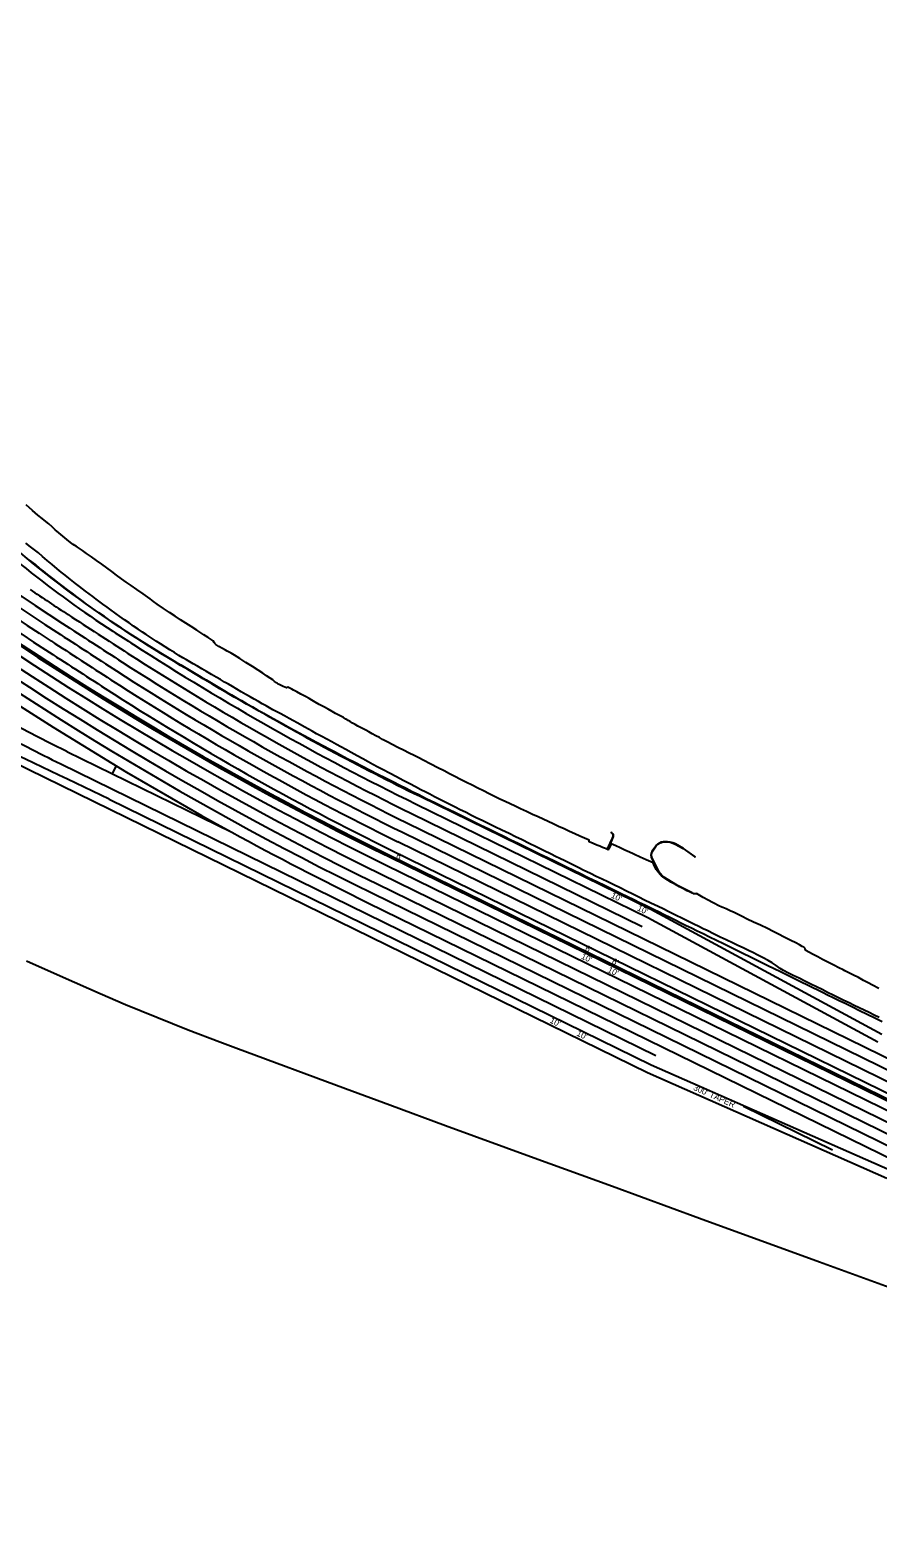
# Model space of a CAD drawing. Extents: x -5665 to 1997148, y 4 to 812485.
# Drawn here: x 1972202 to 1973176, y 793991 to 795722 of the extents above; entities that cross this region are included whole.
import ezdxf

# ---------------------------------------------------------------- set-up
doc = ezdxf.new("R2010")
doc.units = 0
for name, color, linetype in [('RD_EX_Conc', 7, 'Continuous'), ('RD_EX_RailRoad', 7, 'Continuous'), ('RD_EX_Road', 7, 'Continuous'), ('RD_PD_ALT1_TrvlWay', 7, 'Continuous'), ('RD_PD_Final_LnLine', 7, 'Continuous'), ('RD_PD_MedBWall', 7, 'Continuous'), ('RD_PD_PaveShd', 7, 'Continuous'), ('RD_SHT_TX', 7, 'Continuous')]:
    doc.layers.add(name, color=color, linetype=linetype)

msp = doc.modelspace()

# ---------------------------------------------------------------- linework, layer by layer
at = {"layer": 'RD_EX_Conc'}
for points in [[(1972864.5, 794783.6), (1972865.7, 794783.1), (1972867, 794785.4), (1972870, 794792.2), (1972870.2, 794792.5), (1972871.8, 794796.2), (1972871.9, 794797.2), (1972871.8, 794798.4), (1972871.3, 794799.5), (1972870.4, 794800.4), (1972869.4, 794801), (1972870.4, 794800.4), (1972871.3, 794799.5), (1972871.8, 794798.4), (1972872, 794797.2), (1972871.9, 794796.2), (1972870.3, 794792.5), (1972867.1, 794785.4), (1972865.8, 794783), (1972864.5, 794783.5)], [(1972965.3, 794773.6), (1972966, 794773.2), (1972952.5, 794782.7), (1972943.3, 794787.8), (1972940.4, 794789), (1972937.3, 794789.8), (1972934.2, 794790.3), (1972931.7, 794790.3), (1972929.4, 794790.2), (1972927.1, 794789.7), (1972927.1, 794789.7), (1972925, 794788.8), (1972923, 794787.5), (1972921.3, 794786), (1972921.1, 794785.8), (1972916.4, 794779), (1972915.8, 794777.1), (1972915.5, 794775.1), (1972915.7, 794773.1), (1972915.9, 794772.1), (1972924.1, 794756), (1972925.9, 794753.5), (1972928.1, 794751.2), (1972930.5, 794749.3), (1972930.6, 794749.2), (1972945.7, 794740.2), (1972962.5, 794731.9), (1972962.5, 794731.9), (1972945.8, 794740.3), (1972930.7, 794749.3), (1972930.5, 794749.4), (1972928.1, 794751.3), (1972926, 794753.5), (1972924.2, 794756), (1972916, 794772.2), (1972915.8, 794773.1), (1972915.6, 794775.1), (1972915.9, 794777.1), (1972916.5, 794778.9), (1972921.2, 794785.8), (1972921.4, 794785.9), (1972923.1, 794787.5), (1972925, 794788.7), (1972927.1, 794789.6), (1972927.2, 794789.6), (1972929.4, 794790.1), (1972931.7, 794790.2), (1972934.2, 794790.2), (1972937.3, 794789.7), (1972940.3, 794788.9), (1972943.2, 794787.7), (1972952.4, 794782.6), (1972965.3, 794773.6)]]:
    msp.add_lwpolyline(points, dxfattribs=at)
at = {"layer": 'RD_EX_RailRoad'}
msp.add_lwpolyline([(1972198.4, 794653.7), (1972240.5, 794634.8), (1972282.8, 794616.2), (1972311.9, 794603.6), (1972347.9, 794589), (1972384, 794574.6), (1972420.3, 794560.7), (1972438.6, 794553.8), (1972564.6, 794507.3), (1972615.3, 794488.4), (1972679.2, 794464.8), (1972781.1, 794427.7), (1972871, 794395), (1972971, 794358.5), (1973108.6, 794308.1), (1973213.8, 794269.9)], dxfattribs=at)
at = {"layer": 'RD_EX_Road'}
for points in [[(1973176.9, 794622), (1973169.6, 794625.7), (1973164.6, 794628.3), (1973159.1, 794631.3), (1973153.4, 794634.4), (1973147.8, 794637.3), (1973142.5, 794640), (1973138, 794642.3), (1973135.8, 794643.4), (1973130.9, 794645.8), (1973125.3, 794648.6), (1973119.2, 794651.7), (1973112.1, 794655.4), (1973107, 794658.1), (1973100.6, 794661.5), (1973093.1, 794665.6), (1973092.4, 794667.4), (1973092.1, 794667.9), (1973091.9, 794668.2), (1973091.6, 794668.6), (1973091.2, 794669), (1973090.8, 794669.3), (1973088.9, 794670.3), (1973085.8, 794672), (1973081.4, 794674.2), (1973075.8, 794677), (1973068.8, 794680.6), (1973060.8, 794684.8), (1973055.5, 794687.5), (1973048.9, 794690.8), (1973041.1, 794694.5), (1973033.1, 794698.2), (1973025.8, 794701.6), (1973020.1, 794704.4), (1973015.3, 794706.8), (1973010.8, 794709), (1973006.3, 794711.1), (1973001.6, 794713.2), (1972997.9, 794714.8), (1972996.5, 794715.4), (1972995.8, 794715.7), (1972994.1, 794716.5), (1972991.8, 794717.6), (1972989.1, 794719), (1972985.7, 794720.8), (1972981.1, 794723.2), (1972975.1, 794726.5), (1972967.4, 794730.8), (1972967, 794730.7), (1972966.6, 794730.6), (1972965.6, 794730.6), (1972965.1, 794730.6), (1972964.7, 794730.6), (1972964.2, 794730.7), (1972963.8, 794730.9), (1972962.5, 794731.4), (1972960.2, 794732.6), (1972956.9, 794734.2), (1972952.8, 794736.2), (1972948, 794738.7), (1972943.3, 794741.2), (1972938.2, 794744.1), (1972934.5, 794746.2), (1972931.6, 794748), (1972929.4, 794749.6), (1972927.5, 794751.2), (1972925.9, 794752.8), (1972924.4, 794754.6), (1972922.8, 794756.5), (1972921.4, 794758.6), (1972920.2, 794760.7), (1972919, 794763.1), (1972917.6, 794766.2), (1972909.9, 794769.5), (1972902.8, 794772.7), (1972896.4, 794775.6), (1972894.7, 794776.4), (1972890.7, 794778.3), (1972885.3, 794780.8), (1972880, 794783.3), (1972874.8, 794785.7), (1972869.7, 794788), (1972868.5, 794785.4), (1972866.8, 794782.5), (1972866, 794781.2), (1972865.2, 794781.6), (1972863.9, 794782.1), (1972862, 794782.9), (1972859.7, 794783.9), (1972856.7, 794785.1), (1972855.5, 794785.6), (1972853.2, 794786.5), (1972849, 794788.2), (1972844.2, 794790.2), (1972844.3, 794792), (1972839.1, 794794.4), (1972833.5, 794796.9), (1972827.7, 794799.6), (1972821.8, 794802.2), (1972815.7, 794805), (1972809.2, 794808), (1972802.9, 794810.9), (1972797.2, 794813.5), (1972791.6, 794816.1), (1972785.8, 794818.8), (1972779.4, 794821.7), (1972772.4, 794825), (1972765.3, 794828.3), (1972759.2, 794831.1), (1972753.5, 794833.8), (1972747.7, 794836.5), (1972741.7, 794839.4), (1972735.6, 794842.4), (1972729.4, 794845.5), (1972722.9, 794848.7), (1972716.4, 794852), (1972710, 794855.2), (1972703.4, 794858.5), (1972696.7, 794861.9), (1972690, 794865.2), (1972684, 794868.3), (1972677.7, 794871.6), (1972670.5, 794875.3), (1972662.4, 794879.5), (1972653.6, 794884), (1972648.8, 794886.5), (1972643.4, 794889.2), (1972637.6, 794892.2), (1972631.3, 794895.4), (1972625.4, 794898.3), (1972617.5, 794902.4), (1972614, 794904.2), (1972610.8, 794905.9), (1972607.2, 794907.8), (1972603.4, 794909.9), (1972599.2, 794912.1), (1972595.2, 794914.3), (1972591.3, 794916.5), (1972587.9, 794918.3), (1972584.9, 794919.8), (1972581.9, 794921.4), (1972578.8, 794923.1), (1972575.7, 794924.8), (1972572.7, 794926.6), (1972569.9, 794928.3), (1972567.7, 794929.6), (1972566.1, 794930.6), (1972565, 794931.2), (1972562.1, 794932.8), (1972557.6, 794935.3), (1972553.2, 794937.7), (1972549.1, 794940), (1972544.5, 794942.5), (1972539.5, 794945.2), (1972534.5, 794948), (1972529.8, 794950.6), (1972525.9, 794952.8), (1972522.7, 794954.6), (1972518.5, 794956.9), (1972513.2, 794959.8), (1972508.7, 794962.3), (1972504.9, 794964.4), (1972502.9, 794965.5), (1972498.4, 794967.9), (1972496.9, 794967.1), (1972494.9, 794967.9), (1972493.1, 794968.6), (1972491.4, 794969.4), (1972489.9, 794970.1), (1972488.5, 794970.8), (1972487.3, 794971.4), (1972486, 794972.2), (1972485.1, 794972.7), (1972484.2, 794973.4), (1972483.1, 794974.4), (1972481.3, 794976), (1972478, 794978.2), (1972474, 794980.9), (1972469.7, 794983.7), (1972464.4, 794987.1), (1972457.6, 794991.4), (1972450.1, 794996.1), (1972443.2, 795000.6), (1972437.3, 795004.4), (1972433.1, 795006.8), (1972430.4, 795008.3), (1972428.8, 795009.1), (1972426.9, 795010.1), (1972423.2, 795012.2), (1972419.3, 795014.4), (1972416.7, 795016.1), (1972415.7, 795016.9), (1972414.7, 795018), (1972413.8, 795019.2), (1972412.8, 795020.8), (1972406.9, 795024.6), (1972401.8, 795028), (1972393.7, 795033.2), (1972387.3, 795037.3), (1972381.2, 795041.2), (1972375.2, 795045.1), (1972369, 795049.3), (1972362.5, 795053.6), (1972355.7, 795058.2), (1972348.3, 795063.2), (1972344.3, 795066), (1972340.2, 795069), (1972332.1, 795074.8), (1972324.9, 795079.9), (1972318.6, 795084.3), (1972312.9, 795088.3), (1972307.5, 795092.2), (1972301.8, 795096.3), (1972296.1, 795100.5), (1972290.4, 795104.7), (1972284.7, 795108.8), (1972278.8, 795113), (1972273, 795117.2), (1972267.3, 795121.3), (1972262.5, 795124.8), (1972259, 795127.1), (1972256.7, 795128.5), (1972255.3, 795129.5), (1972253.9, 795130.3), (1972252, 795131.6), (1972249, 795133.8), (1972244.7, 795137.2), (1972239.9, 795141.2), (1972235.3, 795145), (1972231.2, 795148.5), (1972227.6, 795151.9), (1972224.1, 795155.1), (1972220.5, 795158.1), (1972216.3, 795161.3), (1972211.4, 795165.3), (1972205.3, 795170.4), (1972197.8, 795176.9)], [(1973177.4, 794588.5), (1973171.5, 794591.4), (1973165.6, 794594.2), (1973159.9, 794597), (1973154.2, 794599.8), (1973148.5, 794602.6), (1973142.7, 794605.4), (1973136.7, 794608.3), (1973130.7, 794611.3), (1973124.4, 794614.3), (1973118.1, 794617.4), (1973111.7, 794620.6), (1973105.2, 794623.8), (1973098.6, 794627), (1973091.9, 794630.3), (1973085.2, 794633.6), (1973078.5, 794636.9), (1973072.4, 794640), (1973067.4, 794642.6), (1973063.6, 794644.9), (1973058.9, 794648.3), (1973054.4, 794651.2), (1973049.7, 794654), (1973044.1, 794657.1), (1973037.3, 794660.6), (1973032.8, 794662.9), (1973027.4, 794665.5), (1973021.2, 794668.5), (1973014.9, 794671.4), (1973009.5, 794674), (1973001.4, 794677.8), (1972994.8, 794680.9), (1972987.7, 794684.4), (1972979.6, 794688.4), (1972975, 794690.6), (1972970.1, 794693.1), (1972964.6, 794695.8), (1972958.3, 794698.9), (1972951.3, 794702.3), (1972943.4, 794706.2), (1972935.8, 794710), (1972929.1, 794713.2), (1972923.5, 794715.9), (1972915.1, 794720), (1972908, 794723.4), (1972901.5, 794726.7), (1972894.6, 794730.1), (1972887.1, 794733.8), (1972879.7, 794737.4), (1972872.6, 794740.8), (1972865.8, 794744.2), (1972859.1, 794747.4), (1972852.5, 794750.6), (1972845.8, 794753.8), (1972837.3, 794757.9), (1972832.3, 794760.4), (1972826.9, 794763), (1972821.6, 794765.6), (1972816.2, 794768.3), (1972810.8, 794771), (1972805.5, 794773.6), (1972800.6, 794776.1), (1972791.7, 794780.5), (1972783.5, 794784.6), (1972775.3, 794788.5), (1972767.4, 794792.4), (1972759.9, 794796.1), (1972752.4, 794799.8), (1972744.2, 794803.6), (1972736, 794807.5), (1972728.5, 794811.2), (1972721.5, 794814.6), (1972715.4, 794817.6), (1972709.3, 794820.6), (1972702.9, 794823.8), (1972695.4, 794827.5), (1972691.2, 794829.6), (1972686.5, 794832), (1972681.9, 794834.3), (1972673.7, 794838.5), (1972666.9, 794841.9), (1972661.4, 794844.8), (1972656.6, 794847.3), (1972651.2, 794850.1), (1972645, 794853.3), (1972638.3, 794856.8), (1972630.9, 794860.6), (1972623.1, 794864.7), (1972615, 794869), (1972607.8, 794872.9), (1972601.8, 794876.1), (1972596.1, 794879.2), (1972590.5, 794882.2), (1972584.4, 794885.5), (1972577.8, 794889.1), (1972571.2, 794892.7), (1972564.8, 794896.3), (1972559.2, 794899.4), (1972554.3, 794902.1), (1972549, 794905), (1972543.1, 794908.2), (1972537.2, 794911.3), (1972531.4, 794914.4), (1972526.3, 794917.2), (1972517.7, 794922), (1972509.1, 794926.9), (1972504.8, 794929.3), (1972500, 794932), (1972494.5, 794934.8), (1972489.5, 794937.5), (1972481.3, 794941.9), (1972473.5, 794946.2), (1972469, 794948.6), (1972464.5, 794951.2), (1972459.8, 794953.9), (1972455, 794956.6), (1972450.1, 794959.5), (1972444.9, 794962.5), (1972439.7, 794965.6), (1972434.8, 794968.4), (1972430.3, 794971.1), (1972425.7, 794973.7), (1972421.1, 794976.4), (1972416, 794979.3), (1972410.6, 794982.4), (1972405.1, 794985.6), (1972399.6, 794988.8), (1972394.5, 794991.7), (1972389.8, 794994.5), (1972382, 794999.1), (1972377.9, 795001.5), (1972373.3, 795004.3), (1972368.3, 795007.4), (1972362.8, 795010.7), (1972357.4, 795014.1), (1972352.1, 795017.4), (1972347.2, 795020.5), (1972342.6, 795023.5), (1972335.6, 795028.2), (1972331.5, 795030.9), (1972326.4, 795034.3), (1972321.2, 795037.9), (1972316.1, 795041.5), (1972310.8, 795045.1), (1972305.6, 795048.8), (1972301.1, 795052.1), (1972293.9, 795057.2), (1972290.9, 795059.4), (1972285.8, 795063.2), (1972278.3, 795068.8), (1972274.3, 795071.7), (1972270.3, 795074.8), (1972266.1, 795077.9), (1972259, 795083.3), (1972254.4, 795086.9), (1972246.8, 795092.8), (1972242.6, 795096.2), (1972238.2, 795099.7), (1972233.4, 795103.7), (1972227.9, 795108.4), (1972222.2, 795113.3), (1972216.8, 795117.7), (1972212, 795121.8), (1972207.6, 795125.3), (1972203, 795128.9), (1972197.5, 795133.1)], [(1973180.7, 794583.7), (1973172.1, 794588), (1973163.4, 794592.2), (1973154.8, 794596.4), (1973146.6, 794600.4), (1973138.8, 794604.2), (1973131.4, 794607.9), (1973124.4, 794611.3), (1973118, 794614.4), (1973112.1, 794617.3), (1973106.7, 794619.9), (1973101.2, 794622.6), (1973094.9, 794625.7), (1973087.8, 794629.2), (1973079.9, 794633.1), (1973071.7, 794637.1), (1973064, 794640.9), (1973056.6, 794644.6), (1973049.6, 794648), (1973042.7, 794651.4), (1973035.7, 794654.9), (1973028.6, 794658.4), (1973021.3, 794661.9), (1973013.9, 794665.6), (1973006.2, 794669.3), (1972998.4, 794673.1), (1972990.4, 794677), (1972982.5, 794680.9), (1972975.1, 794684.5), (1972968.3, 794687.8), (1972961.9, 794691), (1972955.8, 794694), (1972949.6, 794697.1), (1972943.2, 794700.2), (1972936.8, 794703.4), (1972930.5, 794706.5), (1972924.6, 794709.4), (1972918.9, 794712.2), (1972913.6, 794714.8), (1972908.2, 794717.4), (1972902.2, 794720.4), (1972895.5, 794723.6), (1972888.2, 794727.2), (1972880.3, 794731), (1972871.8, 794735.2), (1972862.7, 794739.6), (1972853, 794744.4), (1972843.3, 794749.1), (1972834.5, 794753.4), (1972826.4, 794757.3), (1972819.1, 794760.9), (1972812, 794764.3), (1972804.5, 794768), (1972796.5, 794771.9), (1972788.1, 794775.9), (1972779.6, 794780.1), (1972771.1, 794784.2), (1972762.8, 794788.3), (1972754.5, 794792.3), (1972746.2, 794796.4), (1972737.7, 794800.5), (1972729, 794804.7), (1972720.1, 794809), (1972710.7, 794813.6), (1972700.7, 794818.5), (1972689.9, 794823.8), (1972678.4, 794829.4), (1972667.2, 794834.9), (1972657.3, 794839.8), (1972648.6, 794844.1), (1972641.2, 794847.8), (1972634.2, 794851.3), (1972626.8, 794855), (1972618.8, 794859), (1972610.3, 794863.3), (1972601.6, 794867.7), (1972592.9, 794872.2), (1972584, 794876.7), (1972575.1, 794881.2), (1972566.6, 794885.6), (1972558.9, 794889.7), (1972551.9, 794893.4), (1972545.7, 794896.7), (1972539.2, 794900.2), (1972531.3, 794904.4), (1972522.1, 794909.4), (1972511.5, 794915.1), (1972500.7, 794920.9), (1972490.7, 794926.3), (1972481.6, 794931.3), (1972473.3, 794935.9), (1972465.5, 794940.2), (1972458.1, 794944.4), (1972450.9, 794948.4), (1972444.1, 794952.3), (1972436.9, 794956.4), (1972429, 794961), (1972420.4, 794966), (1972410.9, 794971.6), (1972401.3, 794977.3), (1972392.2, 794982.7), (1972383.5, 794987.9), (1972375.3, 794992.8), (1972367.4, 794997.5), (1972359.8, 795002.1), (1972352.5, 795006.6), (1972345.4, 795010.9), (1972338.3, 795015.4), (1972330.8, 795020.1), (1972323.1, 795025), (1972315.1, 795030.3), (1972307.5, 795035.3), (1972301, 795039.7), (1972295.6, 795043.3), (1972287.7, 795048.7), (1972281.4, 795053), (1972275.7, 795057.1), (1972271.9, 795059.8), (1972267.3, 795063.2), (1972261.8, 795067.2), (1972256.1, 795071.4), (1972250.7, 795075.5), (1972245.5, 795079.4), (1972240.6, 795083.2), (1972236, 795086.7), (1972228.4, 795092.6), (1972222.6, 795097.2), (1972217.9, 795100.9), (1972213.8, 795104.1), (1972208.5, 795108.4), (1972201.8, 795113.7)]]:
    msp.add_lwpolyline(points, dxfattribs=at)
at = {"layer": 'RD_PD_ALT1_TrvlWay'}
for p, q in [((1972244.6, 794894.1), (1972433.9, 794801.5)), ((1972301.1, 794877.6), (1972296.7, 794868.6)), ((1972293.1, 794839.2), (1972915.5, 794534.4)), ((1972645.7, 794833.6), (1972911.6, 794703.4)), ((1972619.3, 794779.7), (1974107.8, 794050.8)), ((1972611.4, 794763.5), (1974099.9, 794034.7)), ((1972911.6, 794703.4), (1973175.7, 794560.7)), ((1972915.5, 794534.4), (1973190.2, 794413.3))]:
    msp.add_line(p, q, dxfattribs=at)
for centre, radius, start, end in [((1974296, 798203.9), 3808.7, 221.351, 236.9714), ((1974296, 798203.9), 3830.7, 221.6979, 243.9112), ((1974296, 798203.9), 3878.7, 222.5846, 241.3089), ((1973117.1, 796676), 1984, 226.1714, 243.9112), ((1972948.6, 796040), 1200, 225.4115, 237.1272), ((1982884.8, 811415.1), 19506.3, 237.12717, 237.21122), ((1982884.8, 811415.1), 19566.3, 236.97136, 237.21122), ((1974047.4, 797696.2), 3187.4, 237.2112, 243.9112), ((1974047.4, 797696.2), 3247.4, 237.2112, 243.9112), ((1969914, 789980.4), 5410, 63.9112, 65.7151)]:
    msp.add_arc(centre, radius, start, end, dxfattribs=at)
at = {"layer": 'RD_PD_Final_LnLine'}
for p, q in [((1972237.6, 794879.8), (1972920.8, 794545.2)), ((1972640.4, 794822.8), (1972905.1, 794693.2)), ((1972635.1, 794812), (1974123.6, 794083.2)), ((1972624.6, 794790.5), (1974113.1, 794061.6)), ((1972629.9, 794801.2), (1974118.3, 794072.4)), ((1972606.1, 794752.7), (1974094.7, 794023.9)), ((1972600.8, 794742), (1974089.3, 794013.1)), ((1972590.3, 794720.4), (1974079, 793991.4)), ((1972595.6, 794731.2), (1974084.3, 794002.2))]:
    msp.add_line(p, q, dxfattribs=at)
for centre, radius, start, end in [((1974296, 798203.9), 3784.7, 220.9822, 236.9714), ((1974296, 798203.9), 3796.7, 221.1811, 236.9714), ((1974296, 798203.9), 3842.7, 221.9056, 243.9112), ((1974296, 798203.9), 3854.7, 222.1089, 243.9112), ((1974296, 798203.9), 3866.7, 222.3682, 243.9112), ((1974296, 798203.9), 3772.7, 227.8993, 236.9714), ((1974296, 798203.9), 3760.7, 236.1738, 236.9714), ((1982884.8, 811415.1), 19518.3, 236.97136, 237.21122), ((1982884.8, 811415.1), 19542.3, 236.97136, 237.21122), ((1982884.8, 811415.1), 19530.3, 236.97136, 237.21122), ((1982884.8, 811415.1), 19554.3, 236.97136, 237.21122), ((1974047.4, 797696.2), 3211.4, 237.2112, 243.9112), ((1974047.4, 797696.2), 3199.4, 237.2112, 243.9112), ((1974047.4, 797696.2), 3235.4, 237.2112, 243.9112), ((1974047.4, 797696.2), 3223.4, 237.2112, 243.9112), ((1973117.1, 796676), 2000, 241.4466, 243.9112), ((1974296, 798203.9), 3878.7, 241.3089, 243.9112)]:
    msp.add_arc(centre, radius, start, end, dxfattribs=at)
at = {"layer": 'RD_PD_MedBWall'}
for p, q in [((1972615.8, 794772.5), (1974104.3, 794043.7)), ((1972616.7, 794774.3), (1974105.1, 794045.5))]:
    msp.add_line(p, q, dxfattribs=at)
for radius, start in [(3820.7, 222.6654), (3818.7, 222.6659)]:
    msp.add_arc((1974296, 798203.9), radius, start, 243.9112, dxfattribs=at)
at = {"layer": 'RD_PD_PaveShd'}
for p, q in [((1972098.2, 794923.5), (1972911.3, 794525.4)), ((1972650.1, 794842.6), (1972915, 794712.9)), ((1972915, 794712.9), (1973180.3, 794569.6)), ((1972911.3, 794525.4), (1973186, 794404.2)), ((1973021.5, 794487), (1973123.7, 794436.9))]:
    msp.add_line(p, q, dxfattribs=at)
for centre, radius, start, end in [((1972996.5, 796085.4), 1256, 225.4115, 239.1338), ((1977787.6, 804101.4), 10594.7, 239.13377, 239.71806), ((1974047.4, 797696.2), 3177.4, 239.7181, 243.9112)]:
    msp.add_arc(centre, radius, start, end, dxfattribs=at)

# ---------------------------------------------------------------- texts
at = {"layer": 'RD_SHT_TX'}
for s, rotation, p in [("6'", 334.1444, (1972621.8, 794771.8)), ("10'", 334.1444, (1972868.7, 794726.6)), ("10'", 334.1444, (1972898.8, 794711.9)), ("6'", 334.1444, (1972838.9, 794665.7)), ("10'", 334.1444, (1972834.4, 794656.6)), ("6'", 334.1444, (1972869.7, 794650.9)), ("10'", 334.1444, (1972864.8, 794641)), ("10'", 334.1444, (1972798.4, 794583)), ("10'", 334.1444, (1972829.2, 794568.2)), ("300' TAPER", 335.9805, (1972963.3, 794505.8))]:
    msp.add_text(s, height=7, rotation=rotation, dxfattribs=at).set_placement(p)

doc.saveas('drawing.dxf')
